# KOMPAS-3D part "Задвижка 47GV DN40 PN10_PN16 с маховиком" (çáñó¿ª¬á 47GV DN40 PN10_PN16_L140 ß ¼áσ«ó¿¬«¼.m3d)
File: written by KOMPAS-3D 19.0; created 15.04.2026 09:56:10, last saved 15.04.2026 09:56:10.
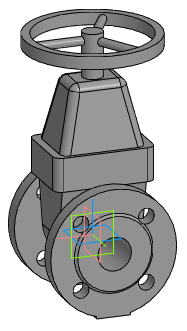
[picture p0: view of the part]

Document properties: Автор: Евгений; Полное имя файла: Z:\3.Личные\kachalov\3d для проектировщиков\2.1 Тип 47GV, 47GV.Z\Задвижка 47GV_DN40-DN600\stp_Задвижка 47GV\Задвижка 47GV DN40 PN10_PN16_L140 с маховиком.m3d

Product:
- Part/product: Задвижка 47GV DN40 PN10_PN16 с маховиком

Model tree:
1. Операция без истории:1  (labels: Задвижка 47GV DN40 PN10_PN16 с маховиком)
